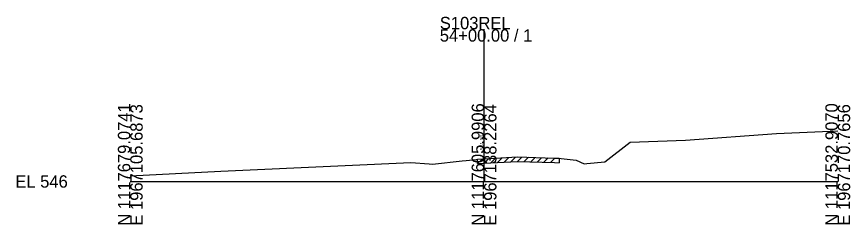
# Model space of a CAD drawing. Extents: x -26 to 163, y -10 to 24518.
# Drawn here: x -25.7 to 162.8, y 4490.3 to 4537.3 of the extents above; entities that cross this region are included whole.
import ezdxf

# ---------------------------------------------------------------- set-up
doc = ezdxf.new("R2010")
doc.units = 0
for name, color, linetype in [('RD_GPK_XS_Cell', 7, 'Continuous'), ('RD_XS_ExGround', 7, 'Continuous'), ('RD_XS_ExPaveRet', 7, 'Continuous'), ('RD_XS_TX_Elev_EX', 7, 'Continuous')]:
    doc.layers.add(name, color=color, linetype=linetype)

msp = doc.modelspace()

# ---------------------------------------------------------------- linework, layer by layer
at = {"layer": 'RD_GPK_XS_Cell'}
for p, q in [((80, 4500), (80, 4534.43)), ((0, 4500), (80, 4500)), ((80, 4500), (160, 4500))]:
    msp.add_line(p, q, dxfattribs=at)
at = {"layer": 'RD_XS_ExGround'}
msp.add_lwpolyline([(0, 4501.29), (20.46, 4502.32), (48.6, 4503.62), (63.42, 4504.3), (67.56, 4503.97), (68.38, 4503.9), (75.04, 4504.64), (75.96, 4504.75), (78.25, 4505), (78.56, 4505.04), (80, 4505.13), (87.6, 4505.55), (95.96, 4505.28), (96.98, 4505.25), (97.42, 4505.2), (100.85, 4504.83), (102.68, 4504), (103.24, 4504.04), (107.29, 4504.45), (113.06, 4508.87), (125.59, 4509.36), (146.12, 4510.82), (160, 4511.48)], dxfattribs=at)
at = {"layer": 'RD_XS_ExPaveRet'}
for p, q in [((78.56, 4504.04), (79.62, 4505.1)), ((78.56, 4504.04), (78.56, 4505.04)), ((78.56, 4504.04), (80, 4504.13)), ((80, 4504.13), (87.6, 4504.55)), ((80.06, 4504.13), (81.12, 4505.19)), ((81.56, 4504.21), (82.62, 4505.27)), ((83.06, 4504.3), (84.12, 4505.36)), ((84.56, 4504.38), (85.62, 4505.44)), ((86.06, 4504.47), (87.12, 4505.53)), ((87.56, 4504.55), (88.53, 4505.52)), ((87.6, 4504.55), (95.96, 4504.28)), ((89.06, 4504.5), (90.03, 4505.47)), ((90.56, 4504.45), (91.53, 4505.42)), ((92.06, 4504.41), (93.03, 4505.37)), ((93.56, 4504.36), (94.53, 4505.32)), ((95.07, 4504.31), (96.03, 4505.28)), ((95.96, 4504.28), (96.98, 4504.25)), ((96.98, 4505.25), (96.98, 4504.25))]:
    msp.add_line(p, q, dxfattribs=at)

# ---------------------------------------------------------------- texts
at = {"layer": 'RD_GPK_XS_Cell'}
for s, p in [('S103REL', (70, 4534.43)), ('54+00.00 / 1', (70, 4531.63)), ('EL 546', (-26, 4498.6))]:
    msp.add_text(s, height=2.8, dxfattribs=at).set_placement(p)
for s, p in [('N 1117679.0741', (0, 4490)), ('E 1967105.6873', (2.8, 4490)), ('N 1117605.9906', (80, 4490)), ('E 1967138.2264', (82.8, 4490)), ('N 1117532.9070', (160, 4490)), ('E 1967170.7656', (162.8, 4490))]:
    msp.add_text(s, height=2.8, rotation=90, dxfattribs=at).set_placement(p)
at = {"layer": 'RD_XS_TX_Elev_EX'}
msp.add_text('551.13', height=0.8, rotation=90, dxfattribs=at).set_placement((79.9, 4507.13))

doc.saveas('drawing.dxf')
